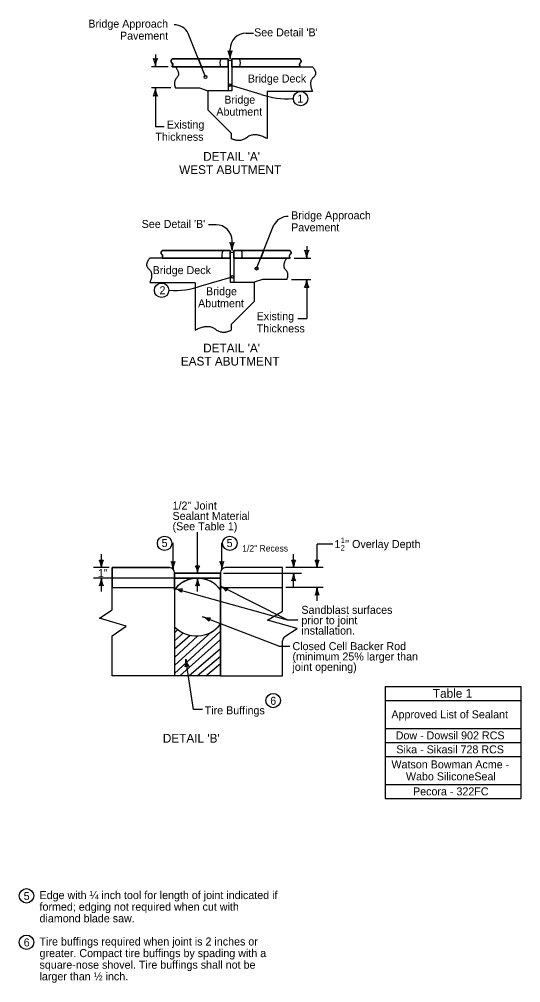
# Model space of a CAD drawing. Extents: x -2933025 to 31692252, y -2344676 to 23854604.
# Drawn here: x -2042330 to -2023531, y -2135530 to -2099417 of the extents above; entities that cross this region are included whole.
import ezdxf

# ---------------------------------------------------------------- set-up
doc = ezdxf.new("R2010")
doc.units = 0
for name, color, linetype in [('Default', 7, 'Continuous'), ('Level 1', 7, 'Continuous'), ('Level 2', 7, 'Continuous'), ('Level 3', 7, 'Continuous')]:
    doc.layers.add(name, color=color, linetype=linetype)

msp = doc.modelspace()

# ---------------------------------------------------------------- linework, layer by layer
at = {"layer": 'Default'}
for p, q in [((-2038842, -2121555), (-2038842, -2119971)), ((-2038842, -2119971), (-2036699, -2119971)), ((-2036507, -2120163), (-2036507, -2120184)), ((-2036507, -2120613), (-2036507, -2120184)), ((-2036507, -2120184), (-2036507, -2124029)), ((-2036507, -2120184), (-2034791, -2120184)), ((-2034791, -2124029), (-2034791, -2120163)), ((-2034791, -2120184), (-2034791, -2120705)), ((-2034791, -2120184), (-2034791, -2120369)), ((-2034791, -2120369), (-2036507, -2120369)), ((-2036507, -2120369), (-2036507, -2120798)), ((-2036507, -2120798), (-2036507, -2120369)), ((-2035655, -2120369), (-2035643, -2120369)), ((-2034791, -2120797), (-2034791, -2120369)), ((-2034791, -2120369), (-2034791, -2120798)), ((-2039319, -2121866), (-2038842, -2121555)), ((-2038321, -2122163), (-2039319, -2121866)), ((-2038842, -2122532), (-2038321, -2122163)), ((-2036509, -2122413), (-2036387, -2122293)), ((-2038842, -2124029), (-2038842, -2122532)), ((-2036510, -2122715), (-2036177, -2122420)), ((-2036510, -2123341), (-2035640, -2122524)), ((-2036509, -2123641), (-2035126, -2122383)), ((-2036509, -2123020), (-2035920, -2122498)), ((-2036507, -2123934), (-2034793, -2122363)), ((-2036307, -2124029), (-2034788, -2122664)), ((-2032457, -2124029), (-2032457, -2122718)), ((-2035968, -2124029), (-2034791, -2123001)), ((-2035664, -2124030), (-2034791, -2123288)), ((-2035337, -2124029), (-2034790, -2123567)), ((-2034791, -2124029), (-2038842, -2124029)), ((-2034791, -2124029), (-2032457, -2124029))]:
    msp.add_line(p, q, dxfattribs=at)
for points in [[(-2034791, -2120664), (-2034791, -2120541), (-2034791, -2120540), (-2034791, -2120537), (-2034791, -2120369), (-2034791, -2120184), (-2036507, -2120184), (-2036507, -2120798)], [(-2034791, -2120163), (-2034791, -2120184), (-2034791, -2120705), (-2034791, -2124029), (-2034930, -2124029)], [(-2032371, -2122558), (-2031906, -2122250), (-2033021, -2121936), (-2032458, -2121605), (-2032457, -2119971), (-2034599, -2119971)], [(-2036507, -2120798), (-2036507, -2120369), (-2035652, -2120369)], [(-2036507, -2120798), (-2036507, -2120369), (-2035652, -2120369)], [(-2036507, -2120798), (-2036507, -2120369), (-2035652, -2120369)], [(-2036507, -2120798), (-2036507, -2120369), (-2035652, -2120369)], [(-2036507, -2120798), (-2036507, -2120369), (-2035652, -2120369)], [(-2035647, -2120369), (-2034791, -2120369), (-2034791, -2120798)], [(-2035647, -2120369), (-2034791, -2120369), (-2034791, -2120537), (-2034791, -2120540), (-2034791, -2120541), (-2034791, -2120798)], [(-2034791, -2120798), (-2034791, -2120797), (-2034791, -2120797), (-2034791, -2120664)]]:
    msp.add_lwpolyline(points, dxfattribs=at)
for centre, radius, start, end in [((-2036699, -2120163), 192, 0, 90), ((-2034599, -2120163), 192, 90, 180), ((-2035649, -2121442), 1073, 36.8603, 143.1397), ((-2035649, -2121442), 1073, 90.1278, 143.139), ((-2035649, -2121442), 1073, 90.1278, 143.139), ((-2035649, -2121442), 1073, 90.1278, 143.1385), ((-2035649, -2121442), 1073, 90.1278, 143.1385), ((-2035649, -2121442), 1073, 98.1344, 143.1385), ((-2035649, -2121442), 1073, 90.3158, 140.4626), ((-2035649, -2121442), 1073, 90.1278, 98.1344), ((-2035649, -2121442), 1073, 36.8603, 89.8704), ((-2035649, -2121442), 1073, 36.8603, 89.8704), ((-2035649, -2121442), 1073, 36.8603, 89.6842), ((-2035649, -2121442), 1073, 140.4626, 143.1385), ((-2035069, -2121199), 603, 62.5774, 63.2482), ((-2034526, -2120123), 603, 243.2482, 243.9147), ((-2032265, -2122718), 192, 123.5371, 180), ((-2032265, -2122718), 192, 123.5371, 180)]:
    msp.add_arc(centre, radius, start, end, dxfattribs=at)
for centre, start_param, end_param in [((-2035688, -2121368), 0.606648, 0.606655), ((-2035688, -2121525), 3.864857, 5.676062)]:
    msp.add_ellipse(centre, major_axis=(1092, 0), ratio=0.91682, start_param=start_param, end_param=end_param, dxfattribs=at)
at = {"layer": 'Level 2'}
for p, q in [((-2035347, -2101581), (-2035994, -2099945)), ((-2033825, -2099936), (-2033547, -2099936)), ((-2034425, -2100905), (-2034425, -2100536)), ((-2037224, -2100740), (-2037224, -2101195)), ((-2034493, -2100905), (-2036600, -2100905)), ((-2034493, -2101195), (-2034493, -2100905)), ((-2034358, -2100959), (-2034493, -2100959)), ((-2031801, -2100905), (-2034358, -2100905)), ((-2034358, -2100905), (-2034358, -2101195)), ((-2036752, -2101195), (-2037375, -2101195)), ((-2036600, -2101195), (-2034493, -2101195)), ((-2034493, -2101195), (-2034493, -2102095)), ((-2034358, -2101195), (-2034358, -2102095)), ((-2034358, -2101195), (-2031801, -2101195)), ((-2031801, -2101195), (-2031339, -2101195)), ((-2036649, -2101990), (-2037375, -2101990)), ((-2037224, -2101990), (-2037224, -2103448)), ((-2036475, -2101990), (-2035572, -2101990)), ((-2035572, -2101990), (-2035258, -2102095)), ((-2034358, -2102095), (-2035258, -2102095)), ((-2035258, -2102095), (-2035258, -2102815)), ((-2033264, -2102232), (-2034425, -2101888)), ((-2033040, -2102115), (-2033040, -2103889)), ((-2033040, -2102115), (-2031339, -2102115)), ((-2032055, -2102392), (-2032083, -2102392)), ((-2035258, -2102815), (-2034390, -2103682)), ((-2036899, -2103448), (-2037224, -2103448)), ((-2034390, -2103682), (-2034390, -2103889)), ((-2034954, -2107118), (-2035232, -2107118)), ((-2033432, -2108763), (-2032785, -2107127)), ((-2034354, -2108087), (-2034354, -2107718)), ((-2036978, -2108087), (-2034422, -2108087)), ((-2034422, -2108087), (-2034422, -2108377)), ((-2034422, -2108141), (-2034287, -2108141)), ((-2034287, -2108377), (-2034287, -2108087)), ((-2034287, -2108087), (-2032180, -2108087)), ((-2031555, -2107922), (-2031555, -2108377)), ((-2036978, -2108377), (-2037440, -2108377)), ((-2034422, -2108377), (-2036978, -2108377)), ((-2034422, -2108377), (-2034422, -2109277)), ((-2034287, -2108377), (-2034287, -2109277)), ((-2032180, -2108377), (-2034287, -2108377)), ((-2032027, -2108377), (-2031404, -2108377)), ((-2035740, -2109297), (-2037440, -2109297)), ((-2035740, -2109297), (-2035740, -2111071)), ((-2035515, -2109414), (-2034355, -2109070)), ((-2034422, -2109277), (-2033522, -2109277)), ((-2033207, -2109172), (-2033522, -2109277)), ((-2033522, -2109277), (-2033522, -2109997)), ((-2032304, -2109172), (-2033207, -2109172)), ((-2032130, -2109172), (-2031404, -2109172)), ((-2031555, -2109172), (-2031555, -2110630)), ((-2036724, -2109574), (-2036696, -2109574)), ((-2033522, -2109997), (-2034390, -2110864)), ((-2031881, -2110630), (-2031555, -2110630)), ((-2034390, -2110864), (-2034390, -2111071)), ((-2028612, -2124422), (-2028612, -2128621)), ((-2028612, -2124422), (-2023531, -2124422)), ((-2023531, -2124422), (-2023531, -2128621)), ((-2028612, -2124946), (-2023531, -2124946)), ((-2028612, -2125996), (-2023531, -2125996)), ((-2028612, -2126521), (-2023531, -2126521)), ((-2028612, -2127046), (-2023531, -2127046)), ((-2028612, -2128096), (-2023531, -2128096)), ((-2028612, -2128621), (-2023531, -2128621))]:
    msp.add_line(p, q, dxfattribs=at)
for points in [[(-2036699, -2119971), (-2038842, -2119971), (-2038842, -2120718), (-2036507, -2120718), (-2036507, -2120611), (-2036507, -2120369), (-2036507, -2120184), (-2036507, -2120163)], [(-2034791, -2120163), (-2034791, -2120184), (-2034791, -2120184), (-2034791, -2120278), (-2034791, -2120611), (-2034791, -2120611), (-2034791, -2120718), (-2032457, -2120718), (-2032457, -2120611), (-2032457, -2119971), (-2034599, -2119971)]]:
    msp.add_lwpolyline(points, dxfattribs=at)
for centre in [(-2035347, -2101581), (-2034425, -2101888), (-2033432, -2108763), (-2034355, -2109070)]:
    msp.add_circle(centre, 53.3, dxfattribs=at)
for centre, radius, start, end in [((-2036526, -2100223), 600, 27.6185, 90), ((-2033825, -2100536), 600, 90, 180), ((-2034425, -2100362), 250, 252.2666, 287.7333), ((-2035073, -2100905), 648, 0, 28.0725), ((-2033777, -2100905), 648, 151.9275, 180), ((-2037224, -2100652), 250, 252.2666, 287.7334), ((-2037872, -2101195), 648, 0, 28.0725), ((-2036576, -2101195), 648, 151.9275, 180), ((-2037872, -2101990), 648, 331.9275, 0), ((-2036576, -2101990), 648, 180, 208.0725), ((-2037224, -2102533), 250, 72.2666, 107.7334), ((-2032277, -2099399), 3000, 250.7941, 273.7021), ((-2032254, -2107405), 600, 90, 152.3815), ((-2034954, -2107718), 600, 0, 90), ((-2034354, -2107544), 250, 252.2667, 287.7334), ((-2035002, -2108087), 648, 0, 28.0725), ((-2033706, -2108087), 648, 151.9275, 180), ((-2031555, -2107834), 250, 252.2666, 287.7333), ((-2032203, -2108377), 648, 360, 28.0725), ((-2030908, -2108377), 648, 151.9275, 180), ((-2032203, -2109172), 648, 331.9275, 360), ((-2030908, -2109172), 648, 180, 208.0725), ((-2036502, -2106581), 3000, 266.2979, 289.2059), ((-2031555, -2109715), 250, 72.2666, 107.7334), ((-2039251, -2119466), 233, 252.2666, 287.7333), ((-2039854, -2119971), 603, 360, 28.0725), ((-2038649, -2119971), 603, 151.9275, 180), ((-2036564, -2119522), 233, 252.2666, 287.7333), ((-2037166, -2120027), 603, 360, 28.0725), ((-2035961, -2120027), 603, 151.9275, 180), ((-2034735, -2119522), 233, 252.2666, 287.7333), ((-2035337, -2120027), 603, 360, 28.0725), ((-2034132, -2120027), 603, 151.9275, 180), ((-2032047, -2119466), 233, 252.2666, 287.7333), ((-2032650, -2119971), 603, 360, 28.0725), ((-2031444, -2119971), 603, 151.9275, 180), ((-2031165, -2119466), 233, 252.2666, 287.7333), ((-2031768, -2119971), 603, 360, 28.0725), ((-2030563, -2119971), 603, 151.9275, 180), ((-2036699, -2120163), 192, 0, 90), ((-2035649, -2119679), 233, 252.2666, 287.7333), ((-2036252, -2120184), 603, 360, 28.0725), ((-2035047, -2120184), 603, 151.9275, 180), ((-2034599, -2120163), 192, 90, 180), ((-2032650, -2120184), 603, 331.9275, 0), ((-2031444, -2120184), 603, 180, 208.0725), ((-2039854, -2120369), 603, 331.9275, 0), ((-2038649, -2120369), 603, 180, 208.0725), ((-2036249, -2120369), 603, 331.9275, 0), ((-2035044, -2120369), 603, 180, 208.0725), ((-2032047, -2120690), 233, 72.2667, 107.7334), ((-2039251, -2120874), 233, 72.2667, 107.7334), ((-2036669, -2121333), 603, 46.3768, 74.4493), ((-2036346, -2120171), 603, 254.4493, 282.5218), ((-2036021, -2120888), 233, 146.716, 182.1827), ((-2035647, -2120874), 233, 72.2667, 107.7334), ((-2035062, -2121203), 603, 35.1757, 63.2482), ((-2034520, -2120126), 603, 243.2482, 271.3206), ((-2034340, -2120892), 233, 135.5148, 170.9815), ((-2031768, -2120718), 603, 331.9275, 0), ((-2030563, -2120718), 603, 180, 208.0725), ((-2031165, -2121223), 233, 72.2667, 107.7334), ((-2035673, -2122374), 603, 40.8833, 68.9558), ((-2035240, -2121249), 603, 248.9558, 277.0283), ((-2034985, -2121993), 233, 141.2225, 176.6892), ((-2036683, -2123493), 603, 340.591, 8.6635), ((-2035492, -2123311), 603, 188.6635, 216.7359), ((-2036011, -2123901), 233, 80.9301, 116.3968)]:
    msp.add_arc(centre, radius, start, end, dxfattribs=at)
for points in [[(-2036600, -2100905), (-2036681, -2101005), (-2036537, -2101088), (-2036600, -2101195)], [(-2031801, -2101195), (-2031847, -2101081), (-2031735, -2101011), (-2031801, -2100905)], [(-2036475, -2101195), (-2036278, -2101471), (-2036568, -2101751), (-2036475, -2101990)], [(-2031339, -2101195), (-2031123, -2101449), (-2031495, -2101749), (-2031339, -2102115)], [(-2033040, -2103889), (-2033522, -2103631), (-2034052, -2104056), (-2034390, -2103889)], [(-2036978, -2108377), (-2036932, -2108263), (-2037044, -2108193), (-2036978, -2108087)], [(-2032180, -2108087), (-2032098, -2108187), (-2032243, -2108270), (-2032180, -2108377)], [(-2037440, -2108377), (-2037656, -2108631), (-2037284, -2108931), (-2037440, -2109297)], [(-2032304, -2108377), (-2032501, -2108653), (-2032212, -2108933), (-2032304, -2109172)], [(-2035740, -2111071), (-2035258, -2110813), (-2034727, -2111238), (-2034390, -2111071)]]:
    msp.add_open_spline(points, degree=2, dxfattribs=at)
at = {"layer": 'Level 3'}
for p, q in [((-2036600, -2100905), (-2035614, -2100905)), ((-2035500, -2101195), (-2035614, -2100905)), ((-2035614, -2100905), (-2034775, -2100905)), ((-2035614, -2100905), (-2035500, -2101195)), ((-2034775, -2100905), (-2034493, -2100905)), ((-2034358, -2100905), (-2034075, -2100905)), ((-2034075, -2100905), (-2031801, -2100905)), ((-2034785, -2101195), (-2035500, -2101195)), ((-2034493, -2101195), (-2034785, -2101195)), ((-2034493, -2101170), (-2034493, -2101195)), ((-2034358, -2101195), (-2034358, -2101170)), ((-2034065, -2101195), (-2034358, -2101195)), ((-2031801, -2101195), (-2034065, -2101195)), ((-2034704, -2108087), (-2036978, -2108087)), ((-2034422, -2108087), (-2034704, -2108087)), ((-2034004, -2108087), (-2034287, -2108087)), ((-2033165, -2108087), (-2034004, -2108087)), ((-2033279, -2108377), (-2033165, -2108087)), ((-2033165, -2108087), (-2033279, -2108377)), ((-2032180, -2108087), (-2033165, -2108087)), ((-2036978, -2108377), (-2034714, -2108377)), ((-2034714, -2108377), (-2034422, -2108377)), ((-2034422, -2108377), (-2034422, -2108352)), ((-2034287, -2108352), (-2034287, -2108377)), ((-2034287, -2108377), (-2033994, -2108377)), ((-2033994, -2108377), (-2033279, -2108377)), ((-2035649, -2120184), (-2035649, -2118640)), ((-2036564, -2120027), (-2036564, -2119044)), ((-2034735, -2120027), (-2034735, -2119044)), ((-2031165, -2119971), (-2031165, -2119087)), ((-2030574, -2119087), (-2031165, -2119087)), ((-2039251, -2119971), (-2039251, -2119468)), ((-2032047, -2119971), (-2032047, -2119468)), ((-2038955, -2119971), (-2039547, -2119971)), ((-2034677, -2120184), (-2031751, -2120184)), ((-2030938, -2119971), (-2032343, -2119971)), ((-2032047, -2120687), (-2032047, -2120184)), ((-2036021, -2120369), (-2039547, -2120369)), ((-2039251, -2120872), (-2039251, -2120369)), ((-2035647, -2120872), (-2035647, -2120369)), ((-2036508, -2120752), (-2032287, -2121927)), ((-2032287, -2121927), (-2034791, -2120664)), ((-2030938, -2120718), (-2032343, -2120718)), ((-2031165, -2121220), (-2031165, -2120718)), ((-2032597, -2122912), (-2035457, -2121812)), ((-2032287, -2121927), (-2031882, -2121929)), ((-2032597, -2122912), (-2032193, -2122915)), ((-2035800, -2125290), (-2036088, -2123402)), ((-2035455, -2125290), (-2035800, -2125290))]:
    msp.add_line(p, q, dxfattribs=at)
for points in [[(-2034493, -2100905), (-2034493, -2100959), (-2034493, -2101170)], [(-2034358, -2101170), (-2034358, -2100959), (-2034358, -2100905)], [(-2035500, -2101195), (-2036475, -2101195), (-2036600, -2101195)], [(-2034422, -2108352), (-2034422, -2108141), (-2034422, -2108087)], [(-2034287, -2108087), (-2034287, -2108141), (-2034287, -2108352)], [(-2033279, -2108377), (-2032304, -2108377), (-2032180, -2108377)]]:
    msp.add_lwpolyline(points, dxfattribs=at)
for centre in [(-2031785, -2102392), (-2036994, -2109574), (-2036882, -2119060), (-2034437, -2119060), (-2032812, -2124954), (-2042060, -2132274), (-2042060, -2134014)]:
    msp.add_circle(centre, 270, dxfattribs=at)
for centre, radius, start, end in [((-2036646, -2100986), 5.71, 309.4114, 37.0697), ((-2034425, -2101063), 384, 155.7088, 200.1278), ((-2034425, -2101063), 384, 155.7088, 200.1278), ((-2034425, -2101063), 384, 339.8722, 24.2912), ((-2034425, -2101063), 384, 339.8722, 24.2912), ((-2034354, -2108245), 384, 155.7088, 200.1278), ((-2034354, -2108245), 384, 155.7088, 200.1278), ((-2034354, -2108245), 384, 339.8722, 24.2912), ((-2034354, -2108245), 384, 339.8722, 24.2912), ((-2032133, -2108168), 5.71, 142.9303, 230.5886)]:
    msp.add_arc(centre, radius, start, end, dxfattribs=at)
for centre, start_param, end_param in [((-2034425, -2101170), 1.570517, 1.570796), ((-2034425, -2101170), 4.71211, 4.712389), ((-2034354, -2108352), 1.570796, 1.571075), ((-2034354, -2108352), 4.712389, 4.712668)]:
    msp.add_ellipse(centre, major_axis=(0, 108), ratio=0.62744, start_param=start_param, end_param=end_param, dxfattribs=at)
for points, degree in [([(-2036600, -2101195), (-2036537, -2101088), (-2036645, -2101026), (-2036643, -2100991)], 3), ([(-2036642, -2100983), (-2036636, -2100950), (-2036600, -2100905)], 2), ([(-2031801, -2100905), (-2031735, -2101011), (-2031847, -2101081), (-2031801, -2101195)], 2), ([(-2036978, -2108087), (-2037044, -2108193), (-2036932, -2108263), (-2036978, -2108377)], 2), ([(-2032180, -2108377), (-2032243, -2108270), (-2032134, -2108208), (-2032136, -2108173)], 3), ([(-2032137, -2108165), (-2032143, -2108132), (-2032180, -2108087)], 2)]:
    msp.add_open_spline(points, degree=degree, dxfattribs=at)

# ---------------------------------------------------------------- texts
at = {"layer": 'Level 1'}
for s, p in [('Edge with ¼ inch tool for length of joint indicated if ', (-2041570, -2132395)), ('formed; edging not required when cut with ', (-2041570, -2132830)), ('diamond blade saw.', (-2041570, -2133265)), ('Tire buffings required when joint is 2 inches or ', (-2041570, -2134135)), ('greater. Compact tire buffings by spading with a ', (-2041570, -2134570)), ('square-nose shovel. Tire buffings shall not be ', (-2041570, -2135005)), ('larger than ½ inch.', (-2041570, -2135440))]:
    msp.add_text(s, height=300, dxfattribs=at).set_placement(p)
at = {"layer": 'Level 2'}
msp.add_text("DETAIL 'B'", height=330, dxfattribs=at).set_placement((-2036947, -2126531))
at = {"layer": 'Level 3'}
for s, height, p in [('Bridge Approach ', 300, (-2039741, -2099733)), ('Pavement', 300, (-2038555, -2100183)), ("See Detail 'B'", 300, (-2033526, -2100057)), ('Bridge Deck', 300, (-2033761, -2101788)), ('Bridge', 300, (-2034644, -2102580)), ('1', 300, (-2031908, -2102542)), ('Abutment', 300, (-2034942, -2103030)), ('Existing', 300, (-2036797, -2103515)), ('Thickness', 300, (-2037229, -2103971)), ("DETAIL 'A'", 330, (-2035436, -2104723)), ('WEST ABUTMENT', 330, (-2036336, -2105218)), ('Bridge Approach ', 300, (-2032138, -2106915)), ("See Detail 'B'", 300, (-2037741, -2107239)), ('Pavement', 300, (-2032138, -2107365)), ('Bridge Deck', 300, (-2037330, -2108970)), ('2', 300, (-2037072, -2109724)), ('Bridge', 300, (-2035329, -2109762)), ('Abutment', 300, (-2035627, -2110212)), ('Existing', 300, (-2033431, -2110697)), ('Thickness', 300, (-2033431, -2111153)), ("DETAIL 'A'", 330, (-2035436, -2111905)), ('EAST ABUTMENT', 330, (-2036273, -2112400)), ('1/2" Joint', 300, (-2036585, -2117795)), ('Sealant Material', 300, (-2036585, -2118183)), ('(See Table 1)', 300, (-2036585, -2118572)), ('5', 300, (-2036995, -2119199)), ('5', 300, (-2034558, -2119199)), ('1', 300, (-2030514, -2119237)), ('1', 210, (-2030281, -2119052)), ("'' Overlay Depth", 300, (-2030118, -2119237)), ('1/2" Recess', 240, (-2033971, -2119368)), ('2', 210, (-2030281, -2119332)), ('1"', 300, (-2039383, -2120325)), ('Sandblast surfaces ', 300, (-2031753, -2121704)), ('prior to joint ', 300, (-2031753, -2122093)), ('installation.', 300, (-2031753, -2122481)), ('Closed Cell Backer Rod ', 300, (-2032088, -2123064)), ('(minimum 25% larger than ', 300, (-2032088, -2123452)), ('joint opening)', 300, (-2032088, -2123840)), ('Table 1', 330, (-2026824, -2124849)), ('6', 300, (-2032920, -2125112)), ('Tire Buffings', 300, (-2035378, -2125470)), ('Approved List of Sealant', 300, (-2028379, -2125621)), ('Dow - Dowsil 902 RCS', 300, (-2028218, -2126409)), ('Sika - Sikasil 728 RCS', 300, (-2028195, -2126934)), ('Watson Bowman Acme - ', 300, (-2028378, -2127496)), ('Wabo SiliconeSeal', 300, (-2027834, -2127946)), ('Pecora - 322FC', 300, (-2027569, -2128508)), ('5', 300, (-2042164, -2132429)), ('6', 300, (-2042163, -2134169))]:
    msp.add_text(s, height=height, dxfattribs=at).set_placement(p)

doc.saveas('drawing.dxf')
